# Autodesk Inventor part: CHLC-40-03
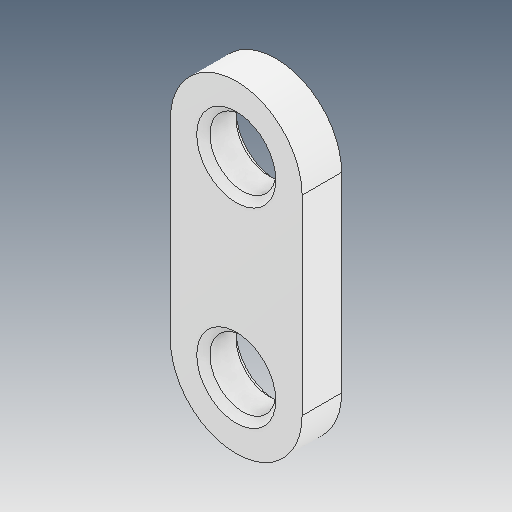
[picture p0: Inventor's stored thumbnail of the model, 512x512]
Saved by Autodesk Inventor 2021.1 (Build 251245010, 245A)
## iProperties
Created: 2021-05
Part Number: CHLC-40-03
Material: Ogólny
Document SubType Name: Modeling
Designer: user
Density: 1 g/cm^3
Appearance: Domyślna
Author: user
Revision Number: ÈÎºÎ
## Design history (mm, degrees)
feature "ÊäÈë1"
node "Bryła1"
